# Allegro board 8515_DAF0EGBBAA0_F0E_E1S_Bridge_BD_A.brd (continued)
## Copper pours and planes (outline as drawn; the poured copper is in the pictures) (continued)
P3V3_E1S_1 on TOP (solid shape): 46.74,41.91 46.74,38.18 46.91,38 50.06,38 50.57,38.51 50.57,38.73 50.83,38.99 51.94,38.99 52.2,38.73 54.36,38.73 54.48,38.61 54.48,38.35 54.43,38.3 52.07,38.3 51.71,37.95 51.51,37.95 50.01,36.45 46.43,36.45 44.62,38.26 42.48,38.26 42.43,38.32 42.43,38.58 42.44,38.6 44.34,38.6 44.49,38.74 44.49,39.1 44.31,39.29 42.97,39.29 42.93,39.33 42.93,39.54 43.01,39.63 44.4,39.63 44.58,39.81 44.58,40.74 44.16,41.16 44.16,41.77 43.79,42.14 43.79,42.67 43.84,42.72 45.92,42.72
P3V3_E1S_2 on TOP (solid shape): 79.91,38.71 79.91,38.3 79.83,38.23 78.21,38.23 77.55,37.57 77.06,37.57 76.3,36.8 76.3,34.38 75.75,33.83 75.58,33.83 75.36,34.05 75.36,37.29 76.57,38.5 76.71,38.5 76.79,38.51 76.89,38.53 77.34,38.53 77.55,38.73 79.88,38.73
P3V3_E1S_2 on TOP (solid shape): 68.21,25.62 69.63,25.62 70.89,24.36 70.89,22.61 70.03,21.74 68.86,21.74 68.54,21.42 64.86,21.42 64.8,21.48 64.8,21.74 64.82,21.76 66.72,21.76 66.87,21.9 66.87,22.26 66.68,22.45 65.34,22.45 65.3,22.49 65.3,22.7 65.34,22.73 66.72,22.73 66.93,22.94 66.93,24.41 66.73,24.61 66.73,25.76 66.83,25.86 67.97,25.86
P3V3_E1S_2 on IN1 (solid shape): outline of 318 points within 68.71,23.71 89.43,39.07
P3V3_E1S_3 on TOP (solid shape): 105.36,38.66 105.36,38.33 105.28,38.25 103.91,38.25 103.12,37.47 102.08,37.47 101.93,37.31 101.93,35.92 101.9,35.89 101.88,35.89 98.3,32.31 98.3,31.58 98.28,31.55 97.27,30.54 97.27,29.53 96.98,29.24 95.73,29.24 95.25,28.75 95.25,27.72 95.1,27.57 91.86,27.57 91.8,27.63 91.8,27.91 91.82,27.93 93.53,27.93 93.59,27.87 94.2,27.87 94.33,28.01 94.33,28.51 94.2,28.65 93.69,28.65 93.65,28.6 92.35,28.6 92.3,28.65 92.3,28.85 92.33,28.88 93.72,28.88 94.06,29.21 94.06,32.21 94.13,32.28 95.07,32.28 95.12,32.23 95.12,31.88 95.63,31.37 96.6,31.37 97.05,31.83 97.05,32.82 100.47,36.24 100.47,37.79 101.19,38.51 101.4,38.71 105.31,38.71
P3V3_EDGE on TOP (solid shape): 26.42,9.65 26.42,4.83 25.91,4.32 24.97,5.25 24.97,9.99 25.15,10.16 25.91,10.16
P3V3_EDGE on TOP (solid shape): 106.3,16.51 106.3,12.95 101.73,8.38 99.82,8.38 96.65,5.21 90.17,5.21 89.41,4.45 89.41,3.56 89.15,3.3 87.38,3.3 87.25,3.43 87.25,5.97 88.65,7.37 95,7.37 97.71,10.08 99.79,10.45 99.91,10.48 100.02,10.53 100.03,10.54 100.2,10.54 103.82,14.16 103.82,15.72 104.04,16.03 104.65,16.64 106.17,16.64
P3V3_EDGE on TOP (solid shape): 127.85,18.42 127.85,16.44 127.95,16.33 128.42,16.33 128.59,16.5 128.59,17.87 128.61,17.89 128.82,17.89 128.88,17.83 128.88,16.94 128.93,16.89 129.24,16.89 129.39,16.74 129.39,16.14 129.39,16.09 129.4,16.04 129.4,14.74 129.74,14.4 129.74,12.84 129.71,12.8 123.55,12.8 122.96,13.39 122.96,13.81 122.96,13.89 122.96,14.71 122.76,14.91 122.28,14.91 122.24,14.91 122.2,14.92 122.16,14.91 122.12,14.91 121.27,14.91 121.22,14.91 121.18,14.92 121.08,14.92 120.9,15.09 120.9,15.54 121.06,15.7 121.06,16.02 121.06,16.08 121.06,16.53 121.06,16.74 121.08,16.76 125.17,16.76 125.53,16.41 125.53,15.98 125.73,15.77 127.08,15.77 127.58,16.27 127.58,18.41 127.64,18.46 127.8,18.46
P3V3_EDGE on IN1 (solid shape): 29.84,12.17 29.84,10.92 29.41,10.49 27.23,10.49 25.54,8.8 24.83,8.8 24.61,9.02 24.61,11.4 25.73,12.52 29.49,12.52
P3V3_EDGE on IN1 (solid shape): outline of 129 points within 56.01,12.35 106.3,18.97
P3V3_EDGE on IN1 (solid shape): 126.34,18.97 126.34,18.38 126.3,18.31 126.22,18.28 126.16,18.29 125.89,18.18 125.78,17.91 125.8,17.79 125.85,17.69 125.86,17.62 125.83,17.56 125.74,17.43 125.7,17.28 125.82,17.01 126.09,16.89 126.15,16.9 126.21,16.91 126.3,16.9 126.34,16.82 126.34,16.69 126.3,16.6 126.2,16.59 126.14,16.61 126.07,16.62 125.69,16.24 126.07,15.86 126.14,15.86 126.2,15.88 126.3,15.87 126.34,15.79 126.34,14.68 126.19,14.53 121.69,14.53 121.04,15.18 121.04,17.4 122.55,18.91 122.58,18.91 122.66,18.87 122.68,18.79 122.68,18.75 122.71,18.61 122.77,18.5 122.8,18.43 122.68,18.11 122.8,17.79 122.77,17.72 122.71,17.61 122.68,17.48 123.06,17.09 123.44,17.48 123.42,17.61 123.35,17.73 123.32,17.79 123.35,17.86 123.42,17.98 123.44,18.11 123.42,18.24 123.35,18.36 123.32,18.43 123.35,18.49 123.42,18.61 123.44,18.75 123.44,18.79 123.47,18.87 123.54,18.91 124.63,18.91 124.75,18.93 124.86,19 125.24,19.38 125.93,19.38
P3V3_EDGE on VCC (solid shape): outline of 2571 points within 104.19,14.06 128.4,22.94
P3V3_EDGE on IN2 (solid shape): 57.53,13.72 57.53,12.95 57.15,12.57 50.8,12.57 49.15,10.92 31.54,10.92 31.43,10.99 31.31,11.02 28.66,11.02 28.08,11.6 28.08,12.84 28.32,13.08 39.86,13.08 39.9,13.08 47.75,13.08 50.29,15.62 55.63,15.62
P12V_AUX on TOP (solid shape): 98.24,61.86 99.05,61.86 99.19,61.72 99.19,60.02 98.93,59.77 98.93,58.32 98.86,58.24 97.9,58.24 97.9,58.85 97.21,59.54 97.21,60.53 96.82,60.92 95.88,60.92 95.57,60.61 95.57,59.67 95.32,59.41 94.9,59.41 94.59,59.11 94.59,56.37 94.54,56.31 94.37,56.31 94.33,56.36 94.33,58.34 94.22,58.45 93.75,58.45 93.59,58.28 93.59,56.91 93.56,56.88 93.36,56.88 93.29,56.95 93.29,57.84 93.25,57.89 92.94,57.89 92.77,58.05 92.77,62.31 93.05,62.59 97.52,62.59
P12V_AUX on TOP (solid shape): 72.71,61.71 73.57,61.71 73.71,61.57 73.71,60.25 73.08,59.61 73.08,59.23 73.46,58.85 73.46,58.17 73.38,58.09 71.77,58.09 71.64,58.22 71.64,60.42 71.35,60.7 69.35,60.7 69.19,60.53 69.19,58.9 69.12,58.83 69.12,56.22 69.06,56.16 68.9,56.16 68.85,56.21 68.85,58.19 68.74,58.29 68.28,58.29 68.11,58.13 68.11,56.76 68.09,56.73 67.88,56.73 67.82,56.8 67.82,57.69 67.77,57.73 67.46,57.73 67.3,57.9 67.3,62.15 67.58,62.43 71.99,62.43
P12V_AUX on TOP (solid shape): 22.12,61.77 23.34,61.77 23.42,61.7 23.42,60.73 23.41,60.72 23.41,60.49 23.19,60.28 22.97,60.28 22.94,60.24 22.94,59.65 23.16,59.42 23.16,58.93 23.06,58.83 22.46,58.83 21.9,59.38 21.9,59.91 21.79,60.02 21.79,60.93 21.69,61.04 20.25,61.04 18.82,59.61 18.82,57.08 18.77,57.03 18.6,57.03 18.56,57.07 18.56,59.05 18.45,59.16 17.98,59.16 17.82,58.99 17.82,57.62 17.79,57.6 17.59,57.6 17.52,57.66 17.52,58.55 17.48,58.6 17.17,58.6 17,58.76 17,62.36 17.22,62.57 21.32,62.57
P12V_AUX on TOP (solid shape): 47.29,61.67 47.96,61.67 48.18,61.44 48.18,60.22 47.93,59.97 47.93,58.14 47.88,58.09 46.93,58.09 46.88,58.15 46.88,58.86 46.16,59.58 46.16,60.65 45.87,60.95 44.6,60.95 44.43,60.78 44.43,60.51 44.42,60.51 44.42,59.81 44.35,59.74 43.99,59.74 43.59,59.34 43.59,56.58 43.53,56.52 43.37,56.52 43.32,56.56 43.32,58.54 43.22,58.65 42.75,58.65 42.58,58.48 42.58,57.11 42.56,57.09 42.35,57.09 42.29,57.15 42.29,58.04 42.24,58.09 41.94,58.09 41.77,58.26 41.77,62.13 42.18,62.53 46.43,62.53
P12V_AUX on TOP (solid shape): 15,34.93 15,34.38 14.81,34.2 14.81,33.77 15,33.58 15.79,33.58 15.8,33.57 15.8,29.75 15.62,29.56 12.93,29.56 12.75,29.74 12.75,30.63 12.73,30.8 12.64,30.94 12.5,31.08 10.3,31.08 10.29,31.07 10.17,31.03 10.07,30.96 9.95,30.84 9.95,28.61 9.89,28.55 9.78,28.55 9.72,28.61 9.72,30.3 9.49,30.54 9.17,30.54 8.97,30.33 8.97,29.05 8.92,29.01 8.75,29.01 8.69,29.06 8.69,30.45 8.51,30.63 7.49,30.63 7.28,30.42 7.28,30.09 7.28,29.99 7.28,29.46 6.96,29.14 1.37,29.14 1.34,29.17 1.34,34.1 1.4,34.16 5.92,34.16 6.5,34.74 6.5,34.9 6.81,35.21 14.71,35.21
P12V_AUX on BOTTOM (solid shape): outline of 481 points within 88.28,53.7 98.51,62.61
P12V_AUX on BOTTOM (solid shape): outline of 634 points within 57.51,46.51 73.33,62.63
P12V_AUX on BOTTOM (solid shape): outline of 4596 points within 6.4,28.69 47.62,62.63
P12V_AUX on VCC (solid shape): outline of 44908 points within 1.02,3.05 146.08,62.88
P12V_AUX on VCC1 (solid shape): outline of 1715 points within 12.64,40.46 100.58,62.88
P12V_E1S_0 on TOP (solid shape): 18.35,58.85 18.35,56.95 18.5,56.8 18.86,56.8 19.05,56.99 19.05,58.33 19.08,58.37 19.3,58.37 19.38,58.28 19.38,56.68 19.99,56.08 20.81,56.08 21.32,56.59 21.32,56.85 21.88,57.41 22.65,57.41 22.68,57.38 22.68,56.06 22.86,55.88 24,55.88 24.13,55.75 24.13,54.36 24,54.23 23.5,54.23 23.44,54.28 23.44,54.48 23.32,54.61 22.78,54.61 22.71,54.53 22.71,54.25 22.68,54.23 21.21,54.23 20.57,53.59 16.48,53.59 16.38,53.7 16.38,55.2 16.51,55.32 16.99,55.32 18.02,56.35 18.02,58.81 18.07,58.87 18.33,58.87
P12V_E1S_0 on BOTTOM (solid shape): 22.45,56.39 22.45,56.13 22.45,56.08 22.45,54.91 22.28,54.74 21.39,54.74 21.35,54.74 21.32,54.73 20.17,54.73 20.17,55.41 20.15,55.53 20.08,55.63 20.06,55.66 20.06,55.93 20.24,56.11 20.25,56.11 20.44,56.22 20.55,56.41 20.55,56.42 20.6,56.46 22.38,56.46
P12V_E1S_0_L on TOP (solid shape): 22.71,52.04 22.74,51.96 22.81,51.92 22.94,51.82 23.1,51.79 23.25,51.82 23.38,51.92 23.45,51.96 23.48,52.04 23.48,52.3 24.11,52.3 24.22,52.19 24.22,50.38 24.12,50.28 22.13,47.26 24.86,44.88 27.34,44.88 27.34,45.06 28.77,45.06 28.96,44.87 28.96,41.43 28.83,41.3 23.72,41.3 20.27,44.75 20.27,45.64 19.71,46.2 19.71,49.39 21.9,51.59 21.9,52.12 22.08,52.3 22.71,52.3
P12V_E1S_1 on TOP (solid shape): 43.12,58.34 43.12,56.44 43.27,56.29 43.62,56.29 43.81,56.48 43.81,57.82 43.85,57.86 44.07,57.86 44.15,57.78 44.15,55.85 44.47,55.53 45.2,55.53 45.87,56.2 45.87,56.21 46.3,56.64 47.37,56.64 47.45,56.57 47.45,55.5 47.7,55.24 48.77,55.24 48.9,55.12 48.9,53.87 48.77,53.75 48.34,53.75 48.23,53.85 48.23,54.1 48.16,54.18 47.37,54.18 47.32,54.13 47.32,53.41 47.23,53.32 46.23,53.32 45.95,53.04 43.18,53.04 42.82,52.68 41.12,52.68 40.84,52.96 40.84,54.31 41.1,54.56 41.51,54.56 42.78,55.83 42.78,58.3 42.84,58.36 43.1,58.36
P12V_E1S_1 on BOTTOM (solid shape): 47.37,56.49 47.37,55.15 46.51,54.29 46.4,54.34 46.27,54.36 46.09,54.32 45.93,54.21 45.2,54.21 45.09,54.19 44.99,54.12 44.85,53.98 44.55,53.98 44.42,54.12 44.42,55.22 44.75,55.56 44.76,55.56 44.95,55.68 45.07,55.87 45.07,55.88 45.81,56.61 47.24,56.61
P12V_E1S_1_L on TOP (solid shape): 47.32,51.74 47.32,51.44 47.42,51.33 48.01,51.33 48.21,51.54 48.21,51.77 48.26,51.82 48.92,51.82 49.05,51.69 49.05,50.05 47.74,48.48 47.87,46.44 47.88,46.43 47.88,46.13 49.2,44.81 54.43,44.81 54.48,44.75 54.48,41.43 54.36,41.3 52.73,41.3 52.7,41.27 51.56,41.27 50.88,41.95 50.8,42.07 50.69,42.15 50.6,42.24 48.62,42.24 45.46,45.4 45.46,48.39 46.41,49.33 46.41,51.54 46.71,51.84 47.22,51.84
P12V_E1S_2 on TOP (solid shape): 68.64,57.99 68.64,56.09 68.79,55.94 69.15,55.94 69.34,56.13 69.34,57.47 69.38,57.5 69.59,57.5 69.68,57.42 69.68,55.82 69.8,55.7 69.79,55.64 69.9,55.38 70.17,55.27 70.22,55.27 70.28,55.22 71.01,55.22 71.46,55.66 71.46,56.42 71.71,56.67 72.9,56.67 72.97,56.59 72.97,53.62 72.52,53.16 69.44,53.16 68.22,51.94 66.55,51.94 66.37,52.12 66.37,54.2 66.63,54.46 67.28,54.46 68.31,55.48 68.31,57.95 68.37,58.01 68.63,58.01
P12V_E1S_2 on TOP (solid shape): 74.01,36.73 74.01,35.19 73.88,35.06 73.28,35.06 73.28,35.57 73.25,35.65 73.19,35.69 73.06,35.79 72.9,35.83 72.74,35.79 72.61,35.69 72.54,35.65 72.52,35.57 72.52,35.06 72.04,35.06 71.85,34.87 71.76,34.87 71.61,34.85 71.49,34.76 71.25,34.52 71.09,34.52 70.95,34.52 70.95,34.51 70.43,34.51 70.43,34.52 70.01,34.51 69.88,34.38 69.32,34.38 69.12,34.38 69.02,34.48 69.02,34.89 70.49,35.15 71.82,35.84 71.9,35.92 71.9,36.82 73.92,36.82
P12V_E1S_2 on BOTTOM (solid shape): 70.07,55.19 70.17,55.18 70.26,55.19 70.36,55.23 70.6,55.23 70.62,55.19 70.65,55.16 71.1,54.71 71.1,54.64 71.16,54.48 71.33,54.41 71.63,54.41 71.79,54.48 71.85,54.64 71.85,54.77 71.88,54.82 71.94,54.81 72.01,54.73 72.01,54.64 72.03,54.55 72.08,54.48 72.08,54.17 72.1,54.05 72.17,53.95 72.44,53.68 72.44,53.19 71.98,52.73 66.88,52.73 66.56,53.05 66.56,55.01 66.77,55.23 69.98,55.23
P12V_E1S_2 on IN2 (solid shape): outline of 185 points within 58.04,31.06 72.66,55.8
P12V_E1S_2_L on TOP (solid shape): 79.88,41.38 79.83,41.33 76.38,41.33 76.05,41.66 76.05,44.37 76.38,44.7 79.88,44.7
P12V_E1S_2_L on TOP (solid shape): 72.52,33.16 72.54,33.08 72.61,33.04 72.74,32.94 72.9,32.91 73.06,32.94 73.19,33.04 73.25,33.08 73.28,33.16 73.28,33.54 74.06,33.54 74.06,32.09 73.5,31.29 71.38,31.29 71.18,31.49 71.2,31.57 71.2,31.62 71.19,31.75 71.14,31.87 71.14,32.6 71.25,32.72 71.27,32.72 71.38,32.79 71.44,32.9 71.44,32.91 71.67,33.13 72.07,33.54 72.52,33.54
P12V_E1S_2_L on IN2 (solid shape): 78.61,43.43 78.61,42.52 76.57,40.47 76.57,35.28 75.94,34.65 75.93,34.64 75.91,34.62 75.88,34.6 75.85,34.59 75.79,34.59 75.74,34.59 75.69,34.57 75.64,34.55 75.59,34.52 75.55,34.48 75.51,34.44 75.48,34.4 75.46,34.35 75.45,34.29 75.44,34.24 75.44,34.18 75.45,34.12 75.47,34.06 72.42,31.01 71.38,31.01 71.12,31.27 71.12,33.36 71.39,33.63 72.21,33.63 72.93,34.35 72.93,39.34 73.96,39.34 73.97,39.29 73.98,39.23 74,39.18 74.03,39.13 74.06,39.09 74.1,39.05 74.15,39.02 74.2,38.99 74.25,38.98 74.3,38.96 74.36,38.96 74.42,38.97 74.47,38.98 74.52,39 74.57,39.03 74.61,39.07 74.65,39.11 74.68,39.16 74.7,39.21 74.72,39.26 74.73,39.32 74.73,39.37 74.72,39.43 74.7,39.48 74.68,39.53 74.65,39.58 74.61,39.62 74.57,39.66 74.52,39.68 74.47,39.71 74.42,39.72 74.36,39.73 74.3,39.72 74.25,39.71 74.2,39.7 74.15,39.67 74.1,39.64 74.06,39.6 74.03,39.56 74,39.51 73.98,39.45 73.97,39.4 73.96,39.34 72.93,39.34 72.93,40.04 76.58,43.69 78.36,43.69
P12V_E1S_3 on TOP (solid shape): 94.12,58.14 94.12,56.24 94.27,56.09 94.63,56.09 94.81,56.28 94.81,57.62 94.85,57.66 95.07,57.66 95.15,57.57 95.15,55.97 95.75,55.37 96.39,55.37 97.34,56.32 97.7,56.32 97.81,56.43 97.81,56.7 97.93,56.82 98.37,56.82 98.45,56.74 98.45,52.8 98.58,52.67 98.58,51.87 98.85,51.61 99.63,51.61 99.88,51.36 99.88,50.15 98.58,48.85 98.58,46.17 99.16,45.59 99.16,44.07 99.09,43.99 98.86,43.99 98.73,43.87 98.73,43.1 98.83,43 99.09,43 99.16,42.93 99.16,42.57 99.03,42.44 96.7,42.44 96.56,42.58 96.56,47.61 96.93,47.98 96.93,49.81 95.71,51.03 93.24,51.03 91.85,52.43 91.85,54.36 92.1,54.61 92.76,54.61 93.78,55.64 93.78,58.1 93.84,58.16 94.1,58.16
P12V_E1S_3 on BOTTOM (solid shape): 95.5,55.81 95.95,55.4 96.41,55.81 96.41,55.85 98.29,55.85 98.29,54.03 97.99,53.72 93.21,53.72 92.91,54.02 92.91,55.68 93.09,55.85 95.49,55.85
P12V_E1S_3_L on TOP (solid shape): 105.36,44.78 105.36,44.33 105.36,44.32 105.36,41.35 105.28,41.27 102.62,41.27 101.98,40.64 100.63,40.64 100.62,40.64 100.13,40.64 99.64,40.16 99.64,40.01 99.42,39.78 99.11,39.78 98.93,39.95 98.93,40.28 100.03,41.38 100.18,41.38 100.35,41.55 100.41,41.6 100.46,41.66 101.04,42.24 101.04,42.82 101.14,42.93 101.42,42.93 101.52,43.03 101.52,43.87 101.45,43.94 101.09,43.94 101.04,43.99 101.04,44.81 101.09,44.86 105.28,44.86
P12V_EDGE on TOP (solid shape): outline of 385 points within 82.85,3.23 86.61,7.59
P12V_EDGE on TOP (solid shape): outline of 515 points within 8.4,3.35 25.2,33.72
P12V_EDGE on BOTTOM (solid shape): 20.96,28.18 20.96,25.77 20.72,25.53 20.72,15.68 19.99,14.95 17.56,14.95 17.41,15.1 17.41,18.35 16.3,19.46 16.3,21.25 15.72,21.82 9.26,21.82 9.14,21.94 9.14,28.01 9.39,28.25 10.6,28.25 10.67,28.23 10.7,28.16 10.72,28.04 10.77,27.93 10.77,27.66 10.81,27.46 10.92,27.3 11.16,27.06 11.16,25.68 11.26,25.57 12.09,25.57 12.27,25.76 12.27,26.03 12.32,26.08 12.75,26.08 13.02,26.34 13.02,28.01 13.04,28.1 13.05,28.19 13.05,28.25 13.19,28.39 20.76,28.39
P12V_EDGE on IN1 (solid shape): outline of 119 points within 8.4,14.92 20.32,33.43
P12V_EDGE on VCC1 (solid shape): outline of 152 points within 1.02,3.05 87.66,27.33
P12V_EDGE on IN2 (solid shape): outline of 110 points within 8.4,17.78 20.32,33.44
P12V_EDGE on IN2 (solid shape): outline of 548 points within 16.18,3.4 24.03,15.7
PVCC_1V2_PLL on BOTTOM (solid shape): 120.38,40.2 120.38,40.2 120.38,40 120.44,39.91 120.61,39.91 120.69,39.95 120.77,39.91 120.88,39.83 121.02,39.79 121.15,39.82 121.25,39.91 121.58,39.91 121.82,39.79 122.05,39.91 122.38,39.91 122.48,39.82 122.62,39.79 122.63,39.79 122.66,39.78 122.68,39.74 122.68,39.56 122.88,39.36 122.93,39.36 122.93,39.34 122.66,39.07 122.65,39.07 122.38,38.8 122.34,38.77 122.15,38.58 121.81,38.24 121.18,38.24 120.89,38.53 120.76,38.62 120.62,38.64 120.11,38.64 119.61,39.15 119.48,39.23 119.34,39.26 119.21,39.26 119,39.47 119,40.31 119.05,40.36 120.22,40.36
PVCC_BIC_SPI on TOP (solid shape): 128.95,53.47 128.95,52.39 128.76,52.2 127.54,52.2 127.4,52.34 127.4,53.55 127.45,53.59 128.83,53.59
PVCC_BIC_SPI on IN1 (solid shape): outline of 328 points within 126.36,42.93 129.29,52.83
BIC_ADCAV33 on BOTTOM (solid shape): outline of 464 points within 118.64,34.77 124.66,37.9
BIC_USB2A_1V2 on BOTTOM (solid shape): outline of 219 points within 122.61,41.48 125.25,47.9
BIC_USB2A_3V3 on BOTTOM (solid shape): 125.94,44.49 125.94,43.71 125.91,43.63 125.83,43.6 125.82,43.61 125.51,43.3 125.82,42.99 125.85,43 125.94,43 125.94,42.88 125.86,42.8 125.75,42.8 125.08,42.8 124.89,42.8 124.89,42.85 124.89,43.57 124.86,43.69 124.8,43.79 124.72,43.87 124.72,44.45 124.84,44.58 125.86,44.58
BIC_USB2A_3V3 on IN1 (solid shape): outline of 304 points within 123.7,40.77 125.9,44.45
OSC1_VDD on TOP (solid shape): 124.46,54.58 124.46,53.95 124.01,53.5 123.97,53.51 123.66,53.38 123.53,53.06 123.53,53.02 123.49,52.98 123.49,52.25 123.44,52.2 122.05,52.2 121.92,52.32 121.92,53.04 121.96,53.12 121.97,53.21 121.97,54.48 123.44,54.48 123.57,54.61 124.43,54.61
OSC1_VDD_R on TOP (solid shape): 124.16,56.13 124.27,56.08 124.39,56.06 124.5,56.08 124.6,56.13 124.62,56.13 124.76,56.13 125.04,56.01 125.32,56.13 126.11,56.13 126.36,55.88 126.36,54.99 126.24,54.86 124.54,54.86 123.82,54.86 123.7,54.99 123.7,56.01 123.83,56.13

Small or netless copper shapes (teardrops, artwork), in the pictures only: 11 on TOP, 5 on BOTTOM, 14 on IN1, 3 on VCC, 6 on IN2

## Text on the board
Ref Des/Silkscreen Bottom: Rev:A | P/N:DAF0EGBBAA0
User.Comments: Baseboard Rev.6B | CR_U7_2 | CR_U7_4 | CR_U7_3 | CR_1_2 | CR_1_3 | CR_U11_2 | CR_1_4 | CR_U11_3 | CR_U11_4 | CR_U16_1 | CR_U4_1 | CR_U4_3 | CR_U4_2 | TEL:(03)327-2345 FAX:(03)397-3614 | NO.211,WENHUA 2ND RD. | GUISHAN DIST.,TAOYUAN | CITY 33377,TAIWAN ( R.O.C.) | IST GERBER(TVX10289A) | Quanta
Ref Des/Silkscreen Top: P/N:DAF0EGBBAA0 | Quanta
User.33: 10.ANY SPECIAL DRILL AND STACKED HOLE PLEASE FOLLOW OUTLINE. PTH TOLERANCE : +/-5(MIL), NPTH TOLERANCE: +/-4(MIL).
User.45: Pin Center | please follow this tolerance and ignore drill chart tolerance | PTH | FIGURE | FINISHED_SIZE | 8.0 | 9.84 | 10.0 | 41.0 | 67.0 | 79.0 | 119.0 | 130.0 | 252.0 | 39.0 | 44.0 | 97.0x44.0 | TOLERANCE_DRILL | +0.0/-8.0 | +2.0/-2.0 | +0.0/-10.0 | +1.96/-1.96 | +3.0/-3.0 | +4.0/-4.0 | +3.0/-0.0 | DRILL CHART: TOP to BOTTOM | ALL UNITS ARE IN MILS | TOLERANCE_TRAVEL | - | PLATED | NON-PLATED | QTY | 34 | 167 | 32 | 245 | 1308 | 4 | 12 | 8 | 2 | 1 | 80
